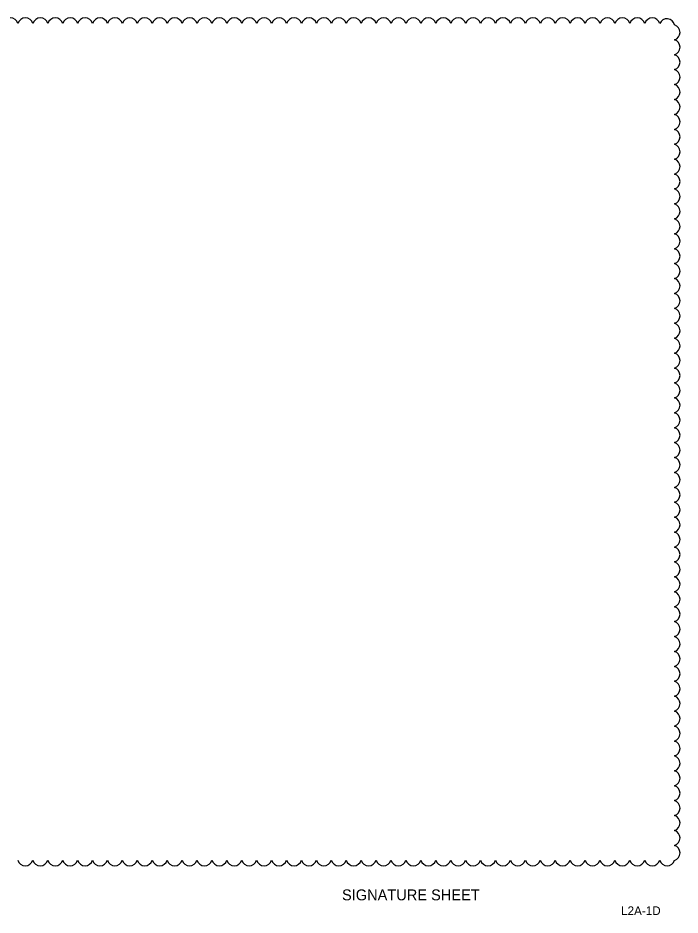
# Model space of a CAD drawing. Extents: x -811 to -790, y -2284 to -2178.
# Drawn here: x -802.91 to -795.32, y -2245.31 to -2235.02 of the extents above; entities that cross this region are included whole.
import ezdxf

# ---------------------------------------------------------------- set-up
doc = ezdxf.new("R2010")
doc.units = 0
for name, color, linetype in [('PlotBorder_dp', 7, 'Continuous'), ('SheetLines_dp', 7, 'Continuous'), ('TextTitle', 7, 'Continuous')]:
    doc.layers.add(name, color=color, linetype=linetype)

msp = doc.modelspace()

# ---------------------------------------------------------------- linework, layer by layer
at = {"layer": 'TextTitle'}
for centre, radius, start, end in [((-803, -2235.106), 0.0897, 17.5, 162.5), ((-802.829, -2235.106), 0.0897, 17.5, 162.5), ((-802.657, -2235.106), 0.0897, 17.5, 162.5), ((-802.486, -2235.106), 0.0897, 17.5, 162.5), ((-802.315, -2235.106), 0.0897, 17.5, 162.5), ((-802.144, -2235.106), 0.0897, 17.5, 162.5), ((-801.973, -2235.106), 0.0897, 17.5, 162.5), ((-801.802, -2235.106), 0.0897, 17.5, 162.5), ((-801.631, -2235.106), 0.0897, 17.5, 162.5), ((-801.46, -2235.106), 0.0897, 17.5, 162.5), ((-801.288, -2235.106), 0.0897, 17.5, 162.5), ((-801.117, -2235.106), 0.0897, 17.5, 162.5), ((-800.946, -2235.106), 0.0897, 17.5, 162.5), ((-800.775, -2235.106), 0.0897, 17.5, 162.5), ((-800.604, -2235.106), 0.0897, 17.5, 162.5), ((-800.433, -2235.106), 0.0897, 17.5, 162.5), ((-800.262, -2235.106), 0.0897, 17.5, 162.5), ((-800.091, -2235.106), 0.0897, 17.5, 162.5), ((-799.919, -2235.106), 0.0897, 17.5, 162.5), ((-799.748, -2235.106), 0.0897, 17.5, 162.5), ((-799.577, -2235.106), 0.0897, 17.5, 162.5), ((-799.406, -2235.106), 0.0897, 17.5, 162.5), ((-799.235, -2235.106), 0.0897, 17.5, 162.5), ((-799.064, -2235.106), 0.0897, 17.5, 162.5), ((-798.893, -2235.106), 0.0897, 17.5, 162.5), ((-798.722, -2235.106), 0.0897, 17.5, 162.5), ((-798.551, -2235.106), 0.0897, 17.5, 162.5), ((-798.379, -2235.106), 0.0897, 17.5, 162.5), ((-798.208, -2235.106), 0.0897, 17.5, 162.5), ((-798.037, -2235.106), 0.0897, 17.5, 162.5), ((-797.866, -2235.106), 0.0897, 17.5, 162.5), ((-797.695, -2235.106), 0.0897, 17.5, 162.5), ((-797.524, -2235.106), 0.0897, 17.5, 162.5), ((-797.353, -2235.106), 0.0897, 17.5, 162.5), ((-797.182, -2235.106), 0.0897, 17.5, 162.5), ((-797.01, -2235.106), 0.0897, 17.5, 162.5), ((-796.839, -2235.106), 0.0897, 17.5, 162.5), ((-796.668, -2235.106), 0.0897, 17.5, 162.5), ((-796.497, -2235.106), 0.0897, 17.5, 162.5), ((-796.326, -2235.106), 0.0897, 17.5, 162.5), ((-796.155, -2235.106), 0.0897, 17.5, 162.5), ((-795.984, -2235.106), 0.0897, 17.5, 162.5), ((-795.813, -2235.106), 0.0897, 17.5, 162.5), ((-795.641, -2235.106), 0.0897, 17.5, 162.5), ((-795.474, -2235.115), 0.0896, 11.7454, 156.7454), ((-795.413, -2235.182), 0.0897, 287.5, 72.5), ((-795.413, -2235.353), 0.0897, 287.5, 72.5), ((-795.413, -2235.524), 0.0897, 287.5, 72.5), ((-795.413, -2235.695), 0.0897, 287.5, 72.5), ((-795.413, -2235.866), 0.0897, 287.5, 72.5), ((-795.413, -2236.038), 0.0897, 287.5, 72.5), ((-795.413, -2236.209), 0.0897, 287.5, 72.5), ((-795.413, -2236.38), 0.0897, 287.5, 72.5), ((-795.413, -2236.551), 0.0897, 287.5, 72.5), ((-795.413, -2236.722), 0.0897, 287.5, 72.5), ((-795.413, -2236.893), 0.0897, 287.5, 72.5), ((-795.413, -2237.064), 0.0897, 287.5, 72.5), ((-795.413, -2237.235), 0.0897, 287.5, 72.5), ((-795.413, -2237.407), 0.0897, 287.5, 72.5), ((-795.413, -2237.578), 0.0897, 287.5, 72.5), ((-795.413, -2237.749), 0.0897, 287.5, 72.5), ((-795.413, -2237.92), 0.0897, 287.5, 72.5), ((-795.413, -2238.091), 0.0897, 287.5, 72.5), ((-795.413, -2238.262), 0.0897, 287.5, 72.5), ((-795.413, -2238.433), 0.0897, 287.5, 72.5), ((-795.413, -2238.604), 0.0897, 287.5, 72.5), ((-795.413, -2238.776), 0.0897, 287.5, 72.5), ((-795.413, -2238.947), 0.0897, 287.5, 72.5), ((-795.413, -2239.118), 0.0897, 287.5, 72.5), ((-795.413, -2239.289), 0.0897, 287.5, 72.5), ((-795.413, -2239.46), 0.0897, 287.5, 72.5), ((-795.413, -2239.631), 0.0897, 287.5, 72.5), ((-795.413, -2239.802), 0.0897, 287.5, 72.5), ((-795.413, -2239.973), 0.0897, 287.5, 72.5), ((-795.413, -2240.144), 0.0897, 287.5, 72.5), ((-795.413, -2240.316), 0.0897, 287.5, 72.5), ((-795.413, -2240.487), 0.0897, 287.5, 72.5), ((-795.413, -2240.658), 0.0897, 287.5, 72.5), ((-795.413, -2240.829), 0.0897, 287.5, 72.5), ((-795.413, -2241), 0.0897, 287.5, 72.5), ((-795.413, -2241.171), 0.0897, 287.5, 72.5), ((-795.413, -2241.342), 0.0897, 287.5, 72.5), ((-795.413, -2241.513), 0.0897, 287.5, 72.5), ((-795.413, -2241.685), 0.0897, 287.5, 72.5), ((-795.413, -2241.856), 0.0897, 287.5, 72.5), ((-795.413, -2242.027), 0.0897, 287.5, 72.5), ((-795.413, -2242.198), 0.0897, 287.5, 72.5), ((-795.413, -2242.369), 0.0897, 287.5, 72.5), ((-795.413, -2242.54), 0.0897, 287.5, 72.5), ((-795.413, -2242.711), 0.0897, 287.5, 72.5), ((-795.413, -2242.882), 0.0897, 287.5, 72.5), ((-795.413, -2243.054), 0.0897, 287.5, 72.5), ((-795.413, -2243.225), 0.0897, 287.5, 72.5), ((-795.413, -2243.396), 0.0897, 287.5, 72.5), ((-795.413, -2243.567), 0.0897, 287.5, 72.5), ((-795.413, -2243.738), 0.0897, 287.5, 72.5), ((-795.413, -2243.909), 0.0897, 287.5, 72.5), ((-795.413, -2244.08), 0.0897, 287.5, 72.5), ((-795.413, -2244.251), 0.0897, 287.5, 72.5), ((-795.413, -2244.423), 0.0897, 287.5, 72.5), ((-795.413, -2244.594), 0.0897, 287.5, 72.5), ((-802.83, -2244.652), 0.0897, 197.5, 342.5), ((-802.658, -2244.652), 0.0897, 197.5, 342.5), ((-802.487, -2244.652), 0.0897, 197.5, 342.5), ((-802.316, -2244.652), 0.0897, 197.5, 342.5), ((-802.145, -2244.652), 0.0897, 197.5, 342.5), ((-801.974, -2244.652), 0.0897, 197.5, 342.5), ((-801.803, -2244.652), 0.0897, 197.5, 342.5), ((-801.632, -2244.652), 0.0897, 197.5, 342.5), ((-801.461, -2244.652), 0.0897, 197.5, 342.5), ((-801.289, -2244.652), 0.0897, 197.5, 342.5), ((-801.118, -2244.652), 0.0897, 197.5, 342.5), ((-800.947, -2244.652), 0.0897, 197.5, 342.5), ((-800.776, -2244.652), 0.0897, 197.5, 342.5), ((-800.605, -2244.652), 0.0897, 197.5, 342.5), ((-800.434, -2244.652), 0.0897, 197.5, 342.5), ((-800.263, -2244.652), 0.0897, 197.5, 342.5), ((-800.092, -2244.652), 0.0897, 197.5, 342.5), ((-799.921, -2244.652), 0.0897, 197.5, 342.5), ((-799.749, -2244.652), 0.0897, 197.5, 342.5), ((-799.578, -2244.652), 0.0897, 197.5, 342.5), ((-799.407, -2244.652), 0.0897, 197.5, 342.5), ((-799.236, -2244.652), 0.0897, 197.5, 342.5), ((-799.065, -2244.652), 0.0897, 197.5, 342.5), ((-798.894, -2244.652), 0.0897, 197.5, 342.5), ((-798.723, -2244.652), 0.0897, 197.5, 342.5), ((-798.552, -2244.652), 0.0897, 197.5, 342.5), ((-798.38, -2244.652), 0.0897, 197.5, 342.5), ((-798.209, -2244.652), 0.0897, 197.5, 342.5), ((-798.038, -2244.652), 0.0897, 197.5, 342.5), ((-797.867, -2244.652), 0.0897, 197.5, 342.5), ((-797.696, -2244.652), 0.0897, 197.5, 342.5), ((-797.525, -2244.652), 0.0897, 197.5, 342.5), ((-797.354, -2244.652), 0.0897, 197.5, 342.5), ((-797.183, -2244.652), 0.0897, 197.5, 342.5), ((-797.011, -2244.652), 0.0897, 197.5, 342.5), ((-796.84, -2244.652), 0.0897, 197.5, 342.5), ((-796.669, -2244.652), 0.0897, 197.5, 342.5), ((-796.498, -2244.652), 0.0897, 197.5, 342.5), ((-796.327, -2244.652), 0.0897, 197.5, 342.5), ((-796.156, -2244.652), 0.0897, 197.5, 342.5), ((-795.985, -2244.652), 0.0897, 197.5, 342.5), ((-795.814, -2244.652), 0.0897, 197.5, 342.5), ((-795.642, -2244.652), 0.0897, 197.5, 342.5), ((-795.471, -2244.652), 0.0897, 197.5, 342.5)]:
    msp.add_arc(centre, radius, start, end, dxfattribs=at)

# ---------------------------------------------------------------- texts
at = {"layer": 'PlotBorder_dp'}
msp.add_text('       SIGNATURE SHEET         ', height=0.125, dxfattribs=at).set_placement((-799.524, -2245.138))
at = {"layer": 'SheetLines_dp'}
msp.add_text('L2A-1D', height=0.1, dxfattribs=at).set_placement((-795.999, -2245.307))

doc.saveas('drawing.dxf')
